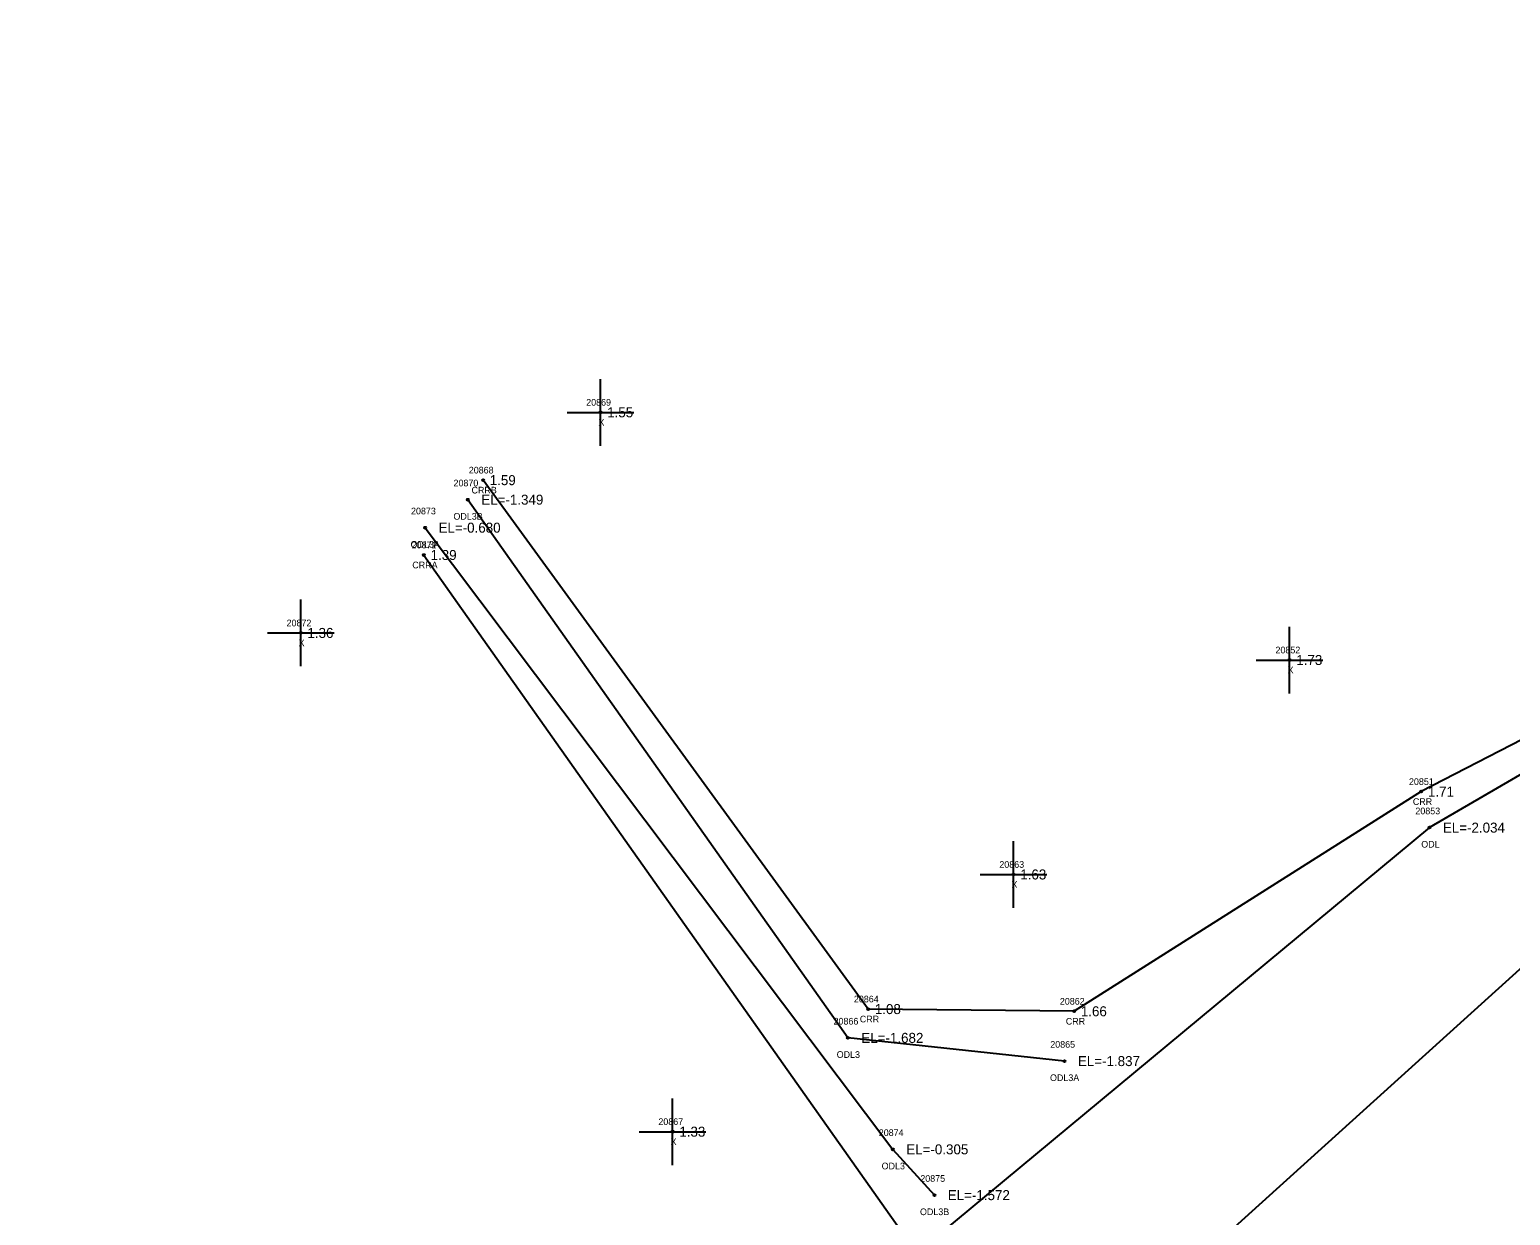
# Model space of a CAD drawing. Extents: x 2608745 to 2610333, y 641917 to 643463.
# Drawn here: x 2609542.9 to 2609764.9, y 642836.7 to 643014.6 of the extents above; entities that cross this region are included whole.
import ezdxf

# ---------------------------------------------------------------- set-up
doc = ezdxf.new("R2010")
doc.units = 0
for name, color, linetype in [('RD_EX_H2O', 7, 'Continuous'), ('RD_EX_H2O_txCode', 7, 'Continuous'), ('RD_EX_Misc', 7, 'Continuous'), ('RD_EX_Misc_txCode', 7, 'Continuous'), ('RD_EX_TX_H2O_ELEV', 7, 'Continuous'), ('RD_EX_TX_Misc_ELEV', 7, 'Continuous'), ('RD_SMD_Locator', 7, 'Continuous')]:
    doc.layers.add(name, color=color, linetype=linetype)

msp = doc.modelspace()

# ---------------------------------------------------------------- linework, layer by layer
at = {"layer": 'RD_EX_H2O'}
for points in [[(2609916.07, 643014.59), (2609838.61, 642951.08), (2609775.14, 642912.46), (2609751.54, 642900.29), (2609699.49, 642867.34), (2609668.6, 642867.67), (2609610.85, 642947.01)], [(2609918.81, 643009.04), (2609840.99, 642946.19), (2609752.78, 642894.89), (2609679.02, 642833.68), (2609605.53, 642770.83), (2609557.42, 642733.27), (2609539.43, 642701.73), (2609511.68, 642671.53), (2609423.05, 642632.06), (2609369.55, 642600.24), (2609327.57, 642579.96), (2609257.07, 642528.8), (2609194.6, 642443.8), (2609156.56, 642341.27)], [(2609920.46, 642991.11), (2609852.12, 642929.11), (2609767.83, 642874.99), (2609693.3, 642807.6), (2609634.08, 642753.09), (2609556.79, 642686.91), (2609524.97, 642657.54), (2609444.81, 642602.16), (2609373.09, 642552.33), (2609285.68, 642492.71), (2609230.49, 642411.33), (2609205.38, 642280.88)], [(2609698.05, 642859.87), (2609665.57, 642863.35), (2609608.58, 642944.08)], [(2609602.17, 642939.88), (2609672.31, 642846.63), (2609678.54, 642839.76)], [(2609601.98, 642935.78), (2609673.88, 642833.93), (2609600.06, 642773.78), (2609552.45, 642739.01), (2609536.34, 642703.62), (2609510.68, 642678.49), (2609498.28, 642669.79)]]:
    msp.add_lwpolyline(points, dxfattribs=at)
at = {"layer": 'RD_EX_Misc'}
for p, q in [((2609628.46, 642952.18), (2609628.46, 642962.18)), ((2609623.46, 642957.18), (2609633.46, 642957.18)), ((2609583.51, 642919.09), (2609583.51, 642929.09)), ((2609578.51, 642924.09), (2609588.51, 642924.09)), ((2609731.8, 642915.03), (2609731.8, 642925.03)), ((2609726.8, 642920.03), (2609736.8, 642920.03)), ((2609690.41, 642882.86), (2609690.41, 642892.86)), ((2609685.41, 642887.86), (2609695.41, 642887.86)), ((2609639.28, 642844.28), (2609639.28, 642854.28)), ((2609634.28, 642849.28), (2609644.28, 642849.28))]:
    msp.add_line(p, q, dxfattribs=at)
at = {"layer": 'RD_SMD_Locator'}
for centre in [(2609628.46, 642957.18), (2609610.85, 642947.01), (2609608.58, 642944.08), (2609602.17, 642939.88), (2609601.98, 642935.78), (2609583.51, 642924.09), (2609731.8, 642920.03), (2609751.54, 642900.29), (2609752.78, 642894.89), (2609690.41, 642887.86), (2609668.6, 642867.67), (2609699.49, 642867.34), (2609665.57, 642863.35), (2609698.05, 642859.87), (2609639.28, 642849.28), (2609672.31, 642846.63), (2609678.54, 642839.76)]:
    msp.add_circle(centre, 0.15, dxfattribs=at)

# ---------------------------------------------------------------- texts
at = {"layer": 'RD_EX_H2O_txCode'}
for s, p in [('20868', (2609608.71, 642948.01)), ('20870', (2609606.42, 642946.08)), ('CRRB', (2609609.12, 642945.01)), ('20873', (2609600.05, 642941.88)), ('ODL3B', (2609606.41, 642941.08)), ('ODL3A', (2609599.98, 642936.88)), ('20871', (2609600.14, 642936.78)), ('CRRA', (2609600.24, 642933.78)), ('20851', (2609749.7, 642901.29)), ('CRR', (2609750.28, 642898.29)), ('20853', (2609750.66, 642896.89)), ('ODL', (2609751.54, 642891.89)), ('20864', (2609666.46, 642868.67)), ('20862', (2609697.35, 642868.34)), ('20866', (2609663.41, 642865.35)), ('CRR', (2609667.35, 642865.67)), ('CRR', (2609698.24, 642865.34)), ('20865', (2609695.91, 642861.87)), ('ODL3', (2609663.88, 642860.35)), ('ODL3A', (2609695.87, 642856.87)), ('20874', (2609670.19, 642848.63)), ('ODL3', (2609670.62, 642843.63)), ('20875', (2609676.42, 642841.76)), ('ODL3B', (2609676.37, 642836.76))]:
    msp.add_text(s, height=1, dxfattribs=at).set_placement(p)
at = {"layer": 'RD_EX_Misc_txCode'}
for s, p in [('20869', (2609626.32, 642958.18)), ('X', (2609628.15, 642955.18)), ('20872', (2609581.39, 642925.09)), ('X', (2609583.19, 642922.09)), ('20852', (2609729.68, 642921.03)), ('X', (2609731.49, 642918.03)), ('20863', (2609688.27, 642888.86)), ('X', (2609690.09, 642885.86)), ('20867', (2609637.14, 642850.28)), ('X', (2609638.97, 642847.28))]:
    msp.add_text(s, height=1, dxfattribs=at).set_placement(p)
at = {"layer": 'RD_EX_TX_H2O_ELEV'}
for s, p in [('1.59', (2609611.85, 642946.26)), ('EL=-1.349', (2609610.58, 642943.33)), ('EL=-0.680', (2609604.17, 642939.13)), ('1.39', (2609602.98, 642935.03)), ('1.71', (2609752.54, 642899.54)), ('EL=-2.034', (2609754.78, 642894.14)), ('1.08', (2609669.6, 642866.92)), ('1.66', (2609700.49, 642866.59)), ('EL=-1.682', (2609667.57, 642862.6)), ('EL=-1.837', (2609700.05, 642859.12)), ('EL=-0.305', (2609674.31, 642845.88)), ('EL=-1.572', (2609680.54, 642839.01))]:
    msp.add_text(s, height=1.5, dxfattribs=at).set_placement(p)
at = {"layer": 'RD_EX_TX_Misc_ELEV'}
for s, p in [('1.55', (2609629.46, 642956.43)), ('1.36', (2609584.51, 642923.34)), ('1.73', (2609732.8, 642919.28)), ('1.63', (2609691.41, 642887.11)), ('1.33', (2609640.28, 642848.53))]:
    msp.add_text(s, height=1.5, dxfattribs=at).set_placement(p)

doc.saveas('drawing.dxf')
